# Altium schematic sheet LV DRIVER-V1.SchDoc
size A3
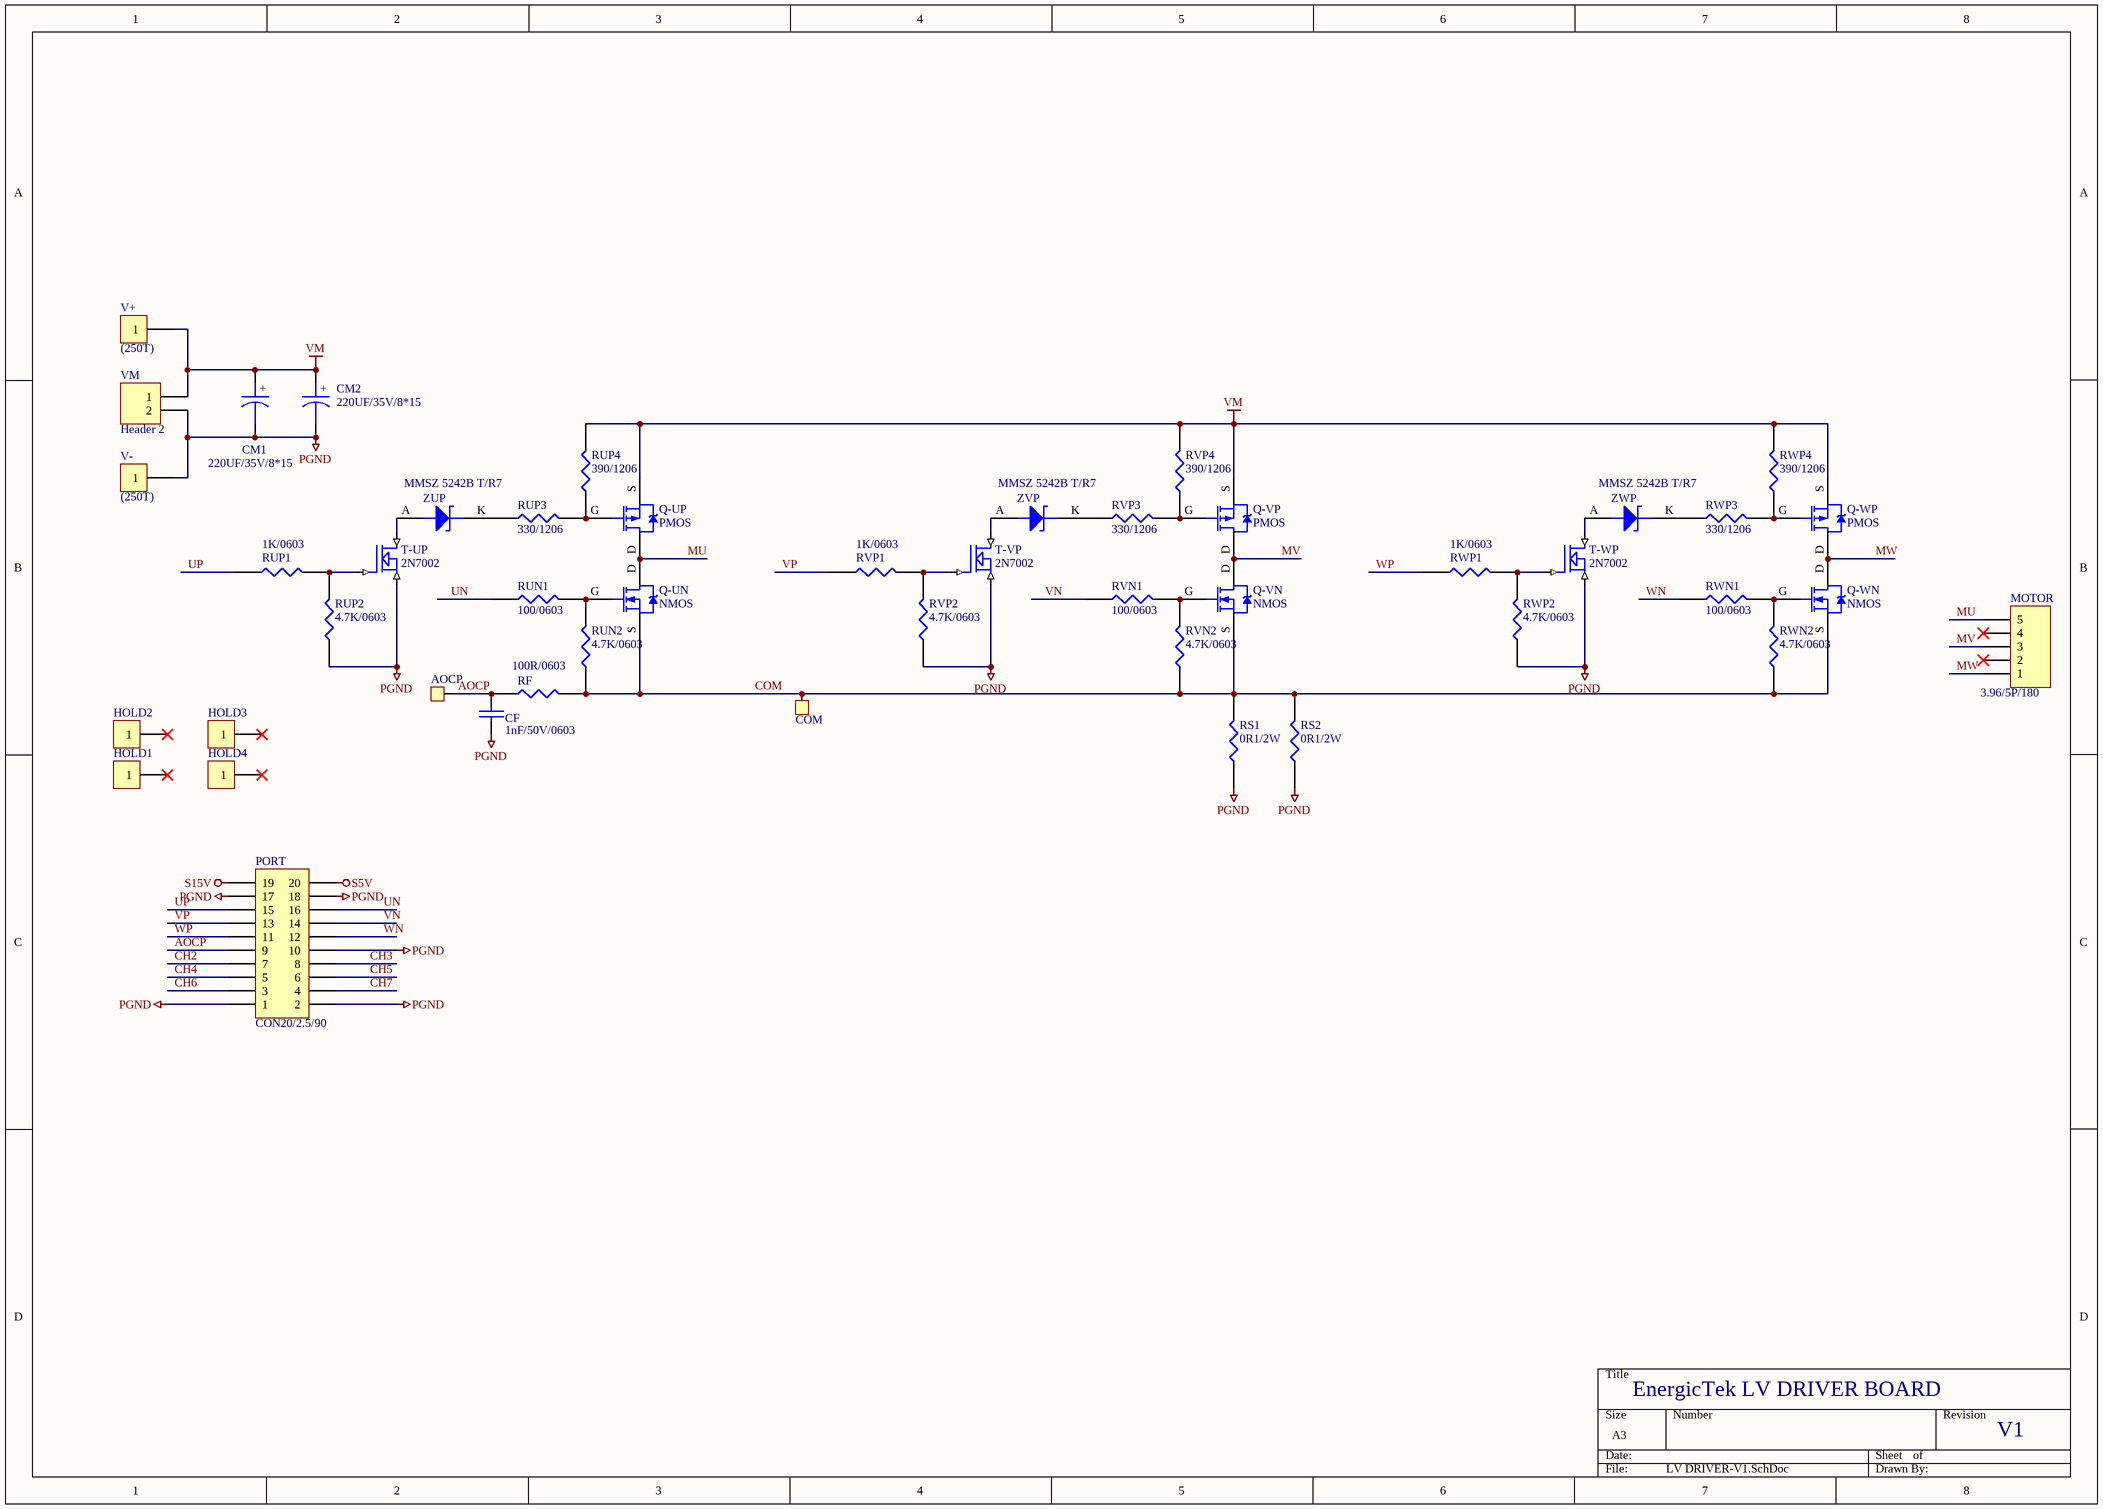
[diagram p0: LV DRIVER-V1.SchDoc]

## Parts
AOCP  (no value)  [TP-R-0.9mm]
CF  1nF/50V/0603  [C0603]
CM1  220UF/35V/8*15  [C-8MM-3.5PITCH]
CM2  220UF/35V/8*15  [C-8MM-3.5PITCH]
COM  (no value)  [TP-R-0.9mm]
HOLD1  TP  [HOLD-3-6]  (value not drawn)
HOLD2  TP  [HOLD-3-6]  (value not drawn)
HOLD3  TP  [HOLD-3-6]  (value not drawn)
HOLD4  TP  [HOLD-3-6]  (value not drawn)
MOTOR  Header 5  [CON-5-2P-3.96]  (value not drawn)
PORT  CON20/2.5/90  [CON-2.54-2x20-90]
Q-UN  NMOS  [TO-252]
Q-UP  PMOS  [TO-252]
Q-VN  NMOS  [TO-252]
Q-VP  PMOS  [TO-252]
Q-WN  NMOS  [TO-252]
Q-WP  PMOS  [TO-252]
RF  100R/0603  [R0603]
RS1  0R1/2W  [R2512]
RS2  0R1/2W  [R2512]
RUN1  100/0603  [R0603]
RUN2  4.7K/0603  [R0603]
RUP1  1K/0603  [R0603]
RUP2  4.7K/0603  [R0603]
RUP3  330/1206  [R1206]
RUP4  390/1206  [R1206]
RVN1  100/0603  [R0603]
RVN2  4.7K/0603  [R0603]
RVP1  1K/0603  [R0603]
RVP2  4.7K/0603  [R0603]
RVP3  330/1206  [R1206]
RVP4  390/1206  [R1206]
RWN1  100/0603  [R0603]
RWN2  4.7K/0603  [R0603]
RWP1  1K/0603  [R0603]
RWP2  4.7K/0603  [R0603]
RWP3  330/1206  [R1206]
RWP4  390/1206  [R1206]
T-UP  2N7002  [QVTO-220A]
T-VP  2N7002  [QVTO-220A]
T-WP  2N7002  [QVTO-220A]
V+  (250T)  [CON-P-850]
V-  (250T)  [CON-P-850]
VM  Header 2  [CON-2P-3.96]
ZUP  MMSZ 5242B T/R7  [D-SOD123]
ZVP  MMSZ 5242B T/R7  [D-SOD123]
ZWP  MMSZ 5242B T/R7  [D-SOD123]

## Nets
PGND: CF.2 CM1.2 CM2.2 PORT.1 PORT.2 PORT.10 PORT.17 PORT.18 RS1.1 RS2.1 RUP2.2 RVP2.2 RWP2.2 T-UP.3(SOURCE) T-VP.3(SOURCE) T-WP.3(SOURCE) V-.1 VM.2
S5V: PORT.20
S15V: PORT.19
VM: CM1.1 CM2.1 Q-UP.S Q-VP.S Q-WP.S RUP4.1 RVP4.1 RWP4.1 V+.1 VM.1
AOCP: AOCP.1 CF.1 PORT.9 RF.1
CH2: PORT.7
CH3: PORT.8
CH4: PORT.5
CH5: PORT.6
CH6: PORT.3
CH7: PORT.4
COM: COM.1 Q-UN.S Q-VN.S Q-WN.S RF.2 RS1.2 RS2.2 RUN2.2 RVN2.2 RWN2.2
MU: MOTOR.5 Q-UN.D Q-UP.D
MV: MOTOR.3 Q-VN.D Q-VP.D
MW: MOTOR.1 Q-WN.D Q-WP.D
UN: PORT.16 RUN1.2
UP: PORT.15 RUP1.2
VN: PORT.14 RVN1.2
VP: PORT.13 RVP1.2
WN: PORT.12 RWN1.2
WP: PORT.11 RWP1.2
NetQ-UN_G: Q-UN.G RUN1.1 RUN2.1
NetQ-UP_G: Q-UP.G RUP3.1 RUP4.2
NetQ-VN_G: Q-VN.G RVN1.1 RVN2.1
NetQ-VP_G: Q-VP.G RVP3.1 RVP4.2
NetQ-WN_G: Q-WN.G RWN1.1 RWN2.1
NetQ-WP_G: Q-WP.G RWP3.1 RWP4.2
NetRUP1_1: RUP1.1 RUP2.1 T-UP.1(GATE)
NetRUP3_2: RUP3.2 ZUP.K
NetRVP1_1: RVP1.1 RVP2.1 T-VP.1(GATE)
NetRVP3_2: RVP3.2 ZVP.K
NetRWP1_1: RWP1.1 RWP2.1 T-WP.1(GATE)
NetRWP3_2: RWP3.2 ZWP.K
NetT-UP_2: T-UP.2(DRAIN) ZUP.A
NetT-VP_2: T-VP.2(DRAIN) ZVP.A
NetT-WP_2: T-WP.2(DRAIN) ZWP.A

Not connected (* = marked no-connect by the designer): HOLD1 1*; HOLD2 1*; HOLD3 1*; HOLD4 1*; MOTOR 2* 4*

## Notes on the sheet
- EnergicTek LV DRIVER BOARD
- V1

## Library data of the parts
AOCP COM = TEST POINT
CF = 1000PF/50V/0603: 1000pF(102)(1n),50V,±10%,X7R,0603,PSA
CM1 CM2 = 100UF/25V/6.3*11: 100uF,25V,LowRES,6.3*11mm,Pitch:2.5,DIP,KY-SERIES
HOLD1-HOLD4 V+ V- = CON1: Connector
MOTOR = Header 5: Header, 5-Pin
PORT = Header 10X2H: Header, 10-Pin, Dual row, Right Angle
Q-UN Q-VN Q-WN = NMOS: N-Channel Power MOSFET
Q-UP Q-VP Q-WP = PMOS: P-Channel Power MOSFET
RF = 100R/0: 100R,1%,0603,PSA,世愛
RS1 RS2 = RES1
RUN1 RUN2 RUP1-RUP4 RVN1 RVN2 RVP1-RVP4 RWN1 RWN2 RWP1-RWP4 = 1M/0603
T-UP T-VP T-WP = MOSN: 5-MOSFET; Text Field1: MITSUBISHI,TOSHIBA,SGS-THOMSON
VM = Header 2: Header, 2-Pin
ZUP ZVP ZWP = ZENER2: Zener Diode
